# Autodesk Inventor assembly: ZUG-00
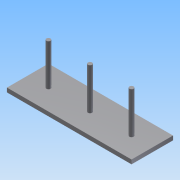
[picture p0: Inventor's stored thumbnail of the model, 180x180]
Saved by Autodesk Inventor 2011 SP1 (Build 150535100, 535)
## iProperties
Created: 2010-12
Part Number: ZUG-00
Document SubType Name: Assembly
Designer: Udo.Huebner
Author: Udo.Huebner
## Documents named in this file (13)
- K:\cadkurs\Inventor\Hanoi\000-Hanoi-IAssembly.iam
- K:\cadkurs\Inventor\Hanoi\001-Halter.ipt
- K:\cadkurs\Inventor\Hanoi\002-Scheiben.ipt
- K:\cadkurs\Inventor\Hanoi\002-Scheiben\Scheibe-01.ipt
- ZUG-00.iam
- ZUG-01.iam
- ZUG-02.iam
- ZUG-03.iam
- ZUG-04.iam
- ZUG-05.iam
- ZUG-06.iam
- ZUG-07.iam
- ZUG-08.iam
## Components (10 placed, 2 different names)
1. 001-Halter:1
2. Scheibe:1
3. Scheibe:2
4. Scheibe:3
5. Scheibe:4
6. Scheibe:5
7. Scheibe:6
8. Scheibe:7
9. Scheibe:8
10. Scheibe:9
